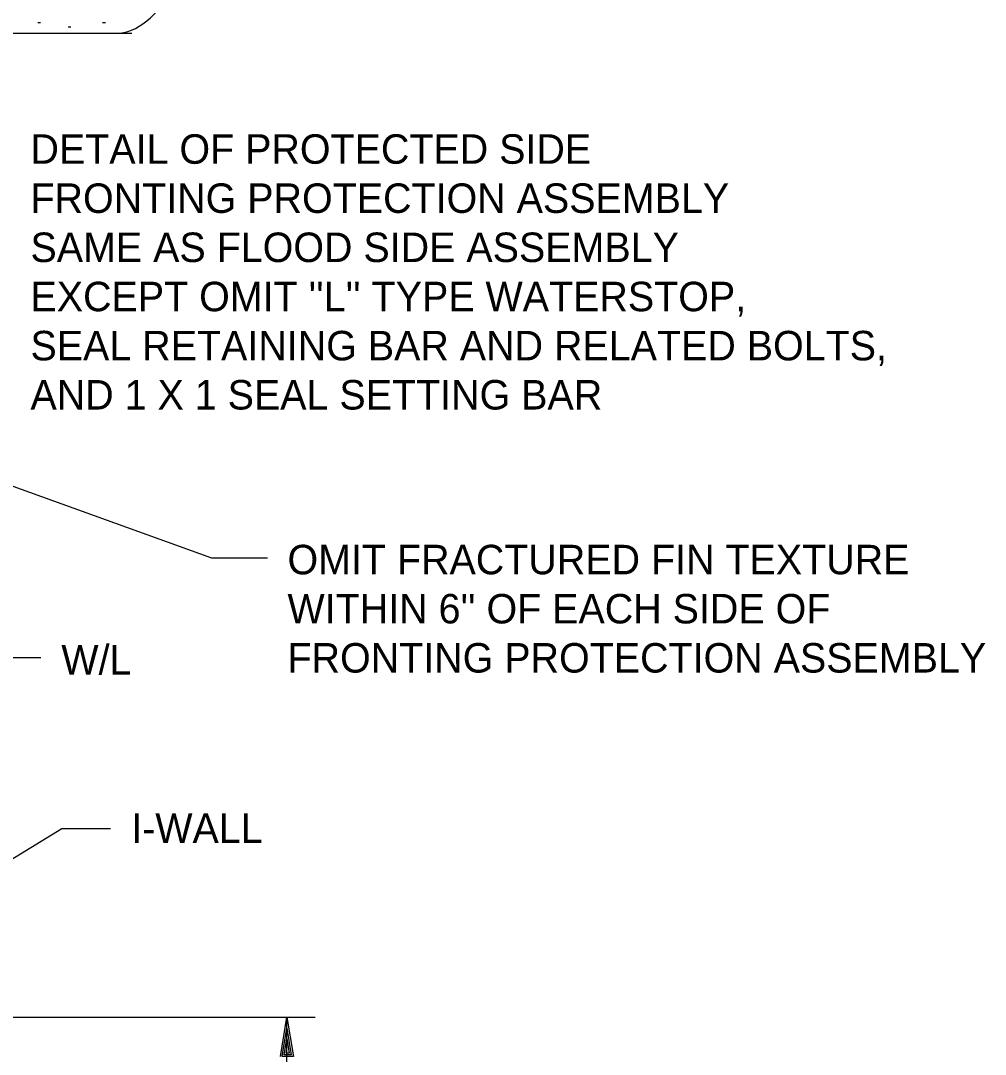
# Model space of a CAD drawing. Extents: x 22388.1 to 22405.7, y 22369.6 to 22390.4.
# Drawn here: x 22404.133 to 22405.667, y 22385.656 to 22387.299 of the extents above; entities that cross this region are included whole.
import ezdxf

# ---------------------------------------------------------------- set-up
doc = ezdxf.new("R2010")
doc.units = 0
for name, color, linetype in [('Level 1', 7, 'Continuous'), ('Level 2', 7, 'Continuous'), ('Level 4', 7, 'Continuous'), ('Level 44', 7, 'Continuous')]:
    doc.layers.add(name, color=color, linetype=linetype)

msp = doc.modelspace()

# ---------------------------------------------------------------- linework, layer by layer
at = {"layer": 'Level 1'}
for p, q in [((22403.482, 22385.7153), (22404.6015, 22385.7153)), ((22404.5563, 22385.5486), (22404.5563, 22385.7153))]:
    msp.add_line(p, q, dxfattribs=at)
msp.add_ellipse((22404.2845, 22387.8418), major_axis=(0, -0.5625), ratio=0.333333, start_param=0, end_param=3.141593, dxfattribs=at)
at = {"layer": 'Level 2'}
for p, q in [((22402.5549, 22387.2793), (22404.3097, 22387.2793)), ((22404.5563, 22385.7153), (22404.5563, 22385.7153)), ((22404.5563, 22385.6979), (22404.5563, 22385.6979))]:
    msp.add_line(p, q, dxfattribs=at)
for points in [[(22404.5257, 22386.4448), (22404.4372, 22386.4448), (22403.7931, 22386.6771)], [(22404.1649, 22386.2865), (22404.0922, 22386.2865), (22403.9195, 22386.1934)], [(22404.2757, 22386.0145), (22404.1984, 22386.0145), (22403.9212, 22385.8453)], [(22404.546, 22385.6529), (22404.5563, 22385.7153), (22404.5667, 22385.6529), (22404.549, 22385.6529), (22404.5563, 22385.6979), (22404.5633, 22385.6556), (22404.552, 22385.6556), (22404.5563, 22385.6813), (22404.56, 22385.6583), (22404.5553, 22385.6583), (22404.5563, 22385.6639)]]:
    msp.add_lwpolyline(points, dxfattribs=at)
at = {"layer": 'Level 44'}
for p, q in [((22404.1602, 22387.2962), (22404.1647, 22387.2962)), ((22404.2084, 22387.2897), (22404.2129, 22387.2897)), ((22404.2634, 22387.2962), (22404.2679, 22387.2962))]:
    msp.add_line(p, q, dxfattribs=at)

# ---------------------------------------------------------------- texts
at = {"layer": 'Level 4'}
for s, height, p in [('DETAIL OF PROTECTED SIDE', 0.046875, (22404.1486, 22387.0718)), ('FRONTING PROTECTION ASSEMBLY', 0.046875, (22404.1486, 22386.9937)), ('SAME AS FLOOD SIDE ASSEMBLY', 0.046875, (22404.1486, 22386.9156)), ("EXCEPT OMIT ''L'' TYPE WATERSTOP,", 0.046875, (22404.1486, 22386.8374)), ('SEAL RETAINING BAR AND RELATED BOLTS,', 0.046875, (22404.1486, 22386.7593)), ('AND 1 X 1 SEAL SETTING BAR', 0.046875, (22404.1486, 22386.6812)), ('OMIT FRACTURED FIN TEXTURE', 0.046875, (22404.5573, 22386.4193)), ("WITHIN 6'' OF EACH SIDE OF", 0.046875, (22404.5573, 22386.3412)), ('W/L', 0.04688, (22404.1977, 22386.26)), ('FRONTING PROTECTION ASSEMBLY', 0.046875, (22404.5573, 22386.2631)), ('I-WALL', 0.04688, (22404.3088, 22385.9923))]:
    msp.add_text(s, height=height, dxfattribs=at).set_placement(p)

doc.saveas('drawing.dxf')
